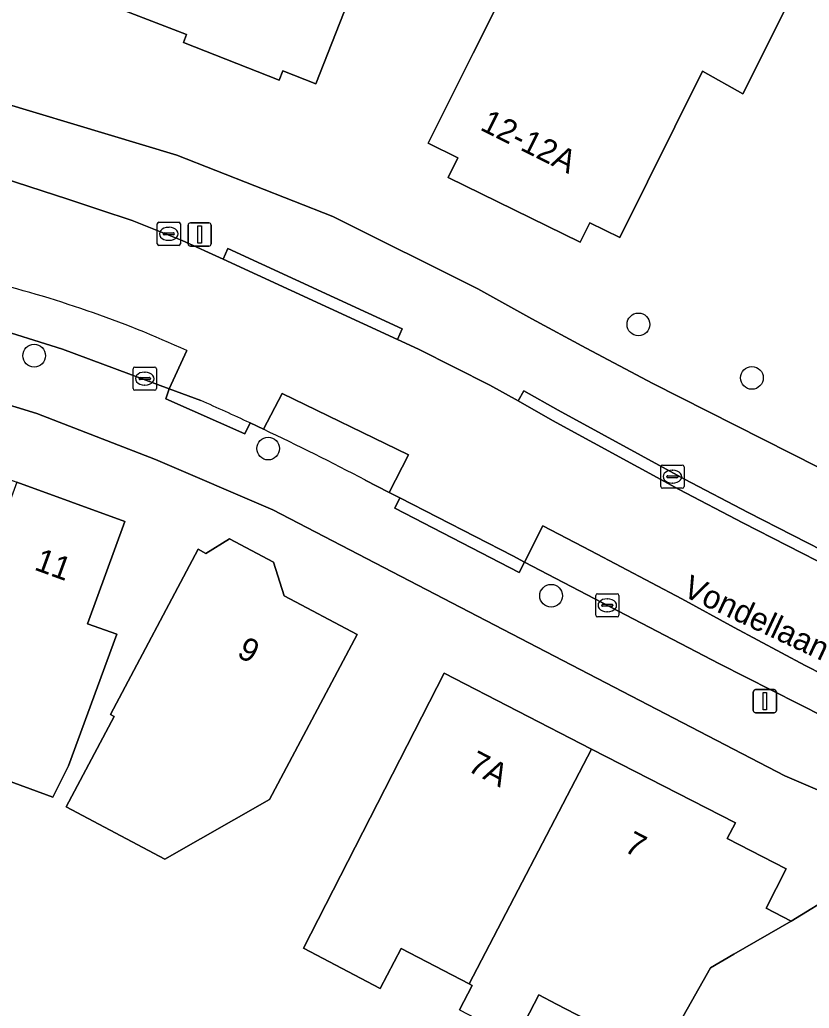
# Model space of a CAD drawing. Extents: x 161347 to 161881, y 382161 to 382804.
# Drawn here: x 161679.82 to 161713.79, y 382471.64 to 382514.18 of the extents above; entities that cross this region are included whole.
import ezdxf

# ---------------------------------------------------------------- set-up
doc = ezdxf.new("R2010")
doc.units = 0
for name, color, linetype in [('IMGEO_Boom', 7, 'Continuous'), ('IMGEO_Erf', 7, 'Continuous'), ('IMGEO_Groenvoorziening', 7, 'Continuous'), ('IMGEO_Kolk', 7, 'Continuous'), ('IMGEO_Lichtmast', 7, 'Continuous'), ('IMGEO_Openbare_ruimte_label', 7, 'Continuous'), ('IMGEO_Pand', 7, 'Continuous'), ('IMGEO_Pand_nummerreeks', 7, 'Continuous'), ('IMGEO_Parkeervlak_open', 7, 'Continuous'), ('IMGEO_Rijbaan_lokaal_open', 7, 'Continuous'), ('IMGEO_Voetpad_open', 7, 'Continuous')]:
    doc.layers.add(name, color=color, linetype=linetype)

msp = doc.modelspace()

# ---------------------------------------------------------------- linework, layer by layer
at = {"layer": 'IMGEO_Boom'}
for centre in [(161706.441, 382501.07), (161680.442, 382499.723), (161711.325, 382498.768), (161690.51, 382495.726), (161702.684, 382489.393)]:
    msp.add_circle(centre, 0.489, dxfattribs=at)
at = {"layer": 'IMGEO_Erf'}
for points in [[(161696.188, 382520.662), (161692.567, 382511.427), (161691.144, 382511.985), (161690.987, 382511.583), (161686.863, 382513.2), (161686.999, 382513.547), (161681.847, 382515.536)], [(161713.495, 382516.124), (161710.939, 382510.999), (161709.201, 382511.967), (161705.646, 382504.803), (161704.346, 382505.443), (161703.935, 382504.612), (161698.261, 382507.398), (161698.673, 382508.24), (161697.4, 382508.875), (161699.331, 382512.737), (161701.067, 382516.209)], [(161671.192, 382513.811), (161672.294, 382513.039), (161676.079, 382511.506), (161686.582, 382508.346), (161693.296, 382505.713), (161699.526, 382502.596), (161701.857, 382501.312), (161704.194, 382500.041), (161707.056, 382498.523), (161714.17, 382494.92), (161716.027, 382493.968), (161718.402, 382492.765), (161721.484, 382491.299)], [(161698.747, 382471.577), (161699.289, 382472.618), (161699.158, 382472.686), (161696.228, 382474.214), (161695.33, 382472.493), (161692.025, 382474.218), (161698.082, 382486.058), (161704.428, 382482.795), (161710.614, 382479.614), (161710.267, 382478.938), (161712.804, 382477.633), (161711.935, 382475.943), (161713.011, 382475.39), (161718.908, 382479.002), (161712.747, 382481.646), (161690.713, 382493.092), (161685.666, 382495.251), (161680.55, 382497.241), (161676.089, 382498.604), (161670.239, 382500), (161669.342, 382500.214)], [(161704.159, 382471.171), (161702.916, 382471.819), (161702.158, 382472.215), (161701.167, 382470.315)]]:
    msp.add_lwpolyline(points, dxfattribs=at)
for points in [[(161669.27, 382483.151), (161672.468, 382492.008), (161673.845, 382491.507), (161675.419, 382495.83), (161679.692, 382494.275), (161684.337, 382492.585), (161682.738, 382488.19), (161683.994, 382487.733), (161681.915, 382482.074), (161681.248, 382480.722), (161677.868, 382481.963), (161675.514, 382482.827), (161675.014, 382481.469)], [(161681.819, 382480.303), (161683.885, 382484.2), (161683.726, 382484.284), (161687.493, 382491.396), (161687.832, 382491.216), (161688.84, 382491.848), (161690.745, 382490.839), (161691.193, 382489.381), (161694.333, 382487.718), (161690.573, 382480.619), (161686.068, 382478.054)]]:
    msp.add_lwpolyline(points, close=True, dxfattribs=at)
at = {"layer": 'IMGEO_Groenvoorziening'}
msp.add_lwpolyline([(161723.237, 382475.454), (161722.614, 382477.411), (161718.908, 382479.002), (161713.011, 382475.39), (161710.549, 382473.96), (161709.541, 382473.374), (161708.224, 382471.041), (161709.207, 382469.376), (161711.307, 382469.157), (161714.949, 382470.071)], close=True, dxfattribs=at)
at = {"layer": 'IMGEO_Kolk'}
for p, q in [((161685.733, 382504.541), (161685.733, 382505.393)), ((161685.808, 382505.467), (161686.66, 382505.467)), ((161686.734, 382505.393), (161686.734, 382504.541)), ((161685.992, 382504.961), (161685.992, 382504.973)), ((161686.035, 382505.01), (161686.433, 382505.01)), ((161686.221, 382505.247), (161686.246, 382505.247)), ((161686.476, 382504.973), (161686.476, 382504.961)), ((161686.43, 382504.924), (161686.032, 382504.924)), ((161686.244, 382504.687), (161686.219, 382504.687)), ((161686.66, 382504.467), (161685.808, 382504.467)), ((161684.699, 382498.309), (161684.699, 382499.161)), ((161684.774, 382499.235), (161685.626, 382499.235)), ((161685.187, 382499.015), (161685.212, 382499.015)), ((161685.7, 382499.161), (161685.7, 382498.309)), ((161684.958, 382498.729), (161684.958, 382498.741)), ((161685.396, 382498.692), (161684.998, 382498.692)), ((161685.001, 382498.778), (161685.399, 382498.778)), ((161685.442, 382498.741), (161685.442, 382498.729)), ((161685.626, 382498.235), (161684.774, 382498.235)), ((161685.21, 382498.455), (161685.185, 382498.455)), ((161707.403, 382494.09), (161707.403, 382494.942)), ((161707.478, 382495.016), (161708.33, 382495.016)), ((161707.891, 382494.796), (161707.916, 382494.796)), ((161708.404, 382494.942), (161708.404, 382494.09)), ((161707.662, 382494.51), (161707.662, 382494.522)), ((161708.1, 382494.473), (161707.702, 382494.473)), ((161707.705, 382494.559), (161708.103, 382494.559)), ((161708.146, 382494.522), (161708.146, 382494.51)), ((161708.33, 382494.016), (161707.478, 382494.016)), ((161707.914, 382494.236), (161707.889, 382494.236)), ((161704.603, 382488.554), (161704.603, 382489.406)), ((161704.678, 382489.48), (161705.53, 382489.48)), ((161705.091, 382489.26), (161705.116, 382489.26)), ((161705.604, 382489.406), (161705.604, 382488.554)), ((161704.862, 382488.974), (161704.862, 382488.986)), ((161705.3, 382488.937), (161704.902, 382488.937)), ((161704.905, 382489.023), (161705.303, 382489.023)), ((161705.346, 382488.986), (161705.346, 382488.974)), ((161705.53, 382488.48), (161704.678, 382488.48)), ((161705.114, 382488.7), (161705.089, 382488.7))]:
    msp.add_line(p, q, dxfattribs=at)
for points in [[(161685.733, 382504.541), (161685.733, 382505.393)], [(161685.808, 382505.467), (161686.66, 382505.467)], [(161686.734, 382505.393), (161686.734, 382504.541)], [(161686.66, 382504.467), (161685.808, 382504.467)], [(161684.699, 382498.309), (161684.699, 382499.161)], [(161684.774, 382499.235), (161685.626, 382499.235)], [(161685.7, 382499.161), (161685.7, 382498.309)], [(161685.626, 382498.235), (161684.774, 382498.235)], [(161707.403, 382494.09), (161707.403, 382494.942)], [(161707.478, 382495.016), (161708.33, 382495.016)], [(161708.404, 382494.942), (161708.404, 382494.09)], [(161708.33, 382494.016), (161707.478, 382494.016)], [(161704.603, 382488.554), (161704.603, 382489.406)], [(161704.678, 382489.48), (161705.53, 382489.48)], [(161705.604, 382489.406), (161705.604, 382488.554)], [(161705.53, 382488.48), (161704.678, 382488.48)]]:
    msp.add_lwpolyline(points, dxfattribs=at)
for centre, radius, start, end in [((161685.81, 382505.391), 0.0765, 91.552, 178.448), ((161685.81, 382505.391), 0.0765, 91.552, 178.448), ((161686.658, 382505.391), 0.0765, 1.552, 88.448), ((161686.658, 382505.391), 0.0765, 1.552, 88.448), ((161686.032, 382504.97), 0.0403, 85.8775, 175.7526), ((161686.029, 382504.96), 0.0366, 178.938, 274.7102), ((161686.433, 382504.967), 0.043, 264.8664, 352.4533), ((161686.437, 382504.972), 0.0386, 1.7309, 96.639), ((161685.81, 382504.543), 0.0765, 181.552, 268.448), ((161685.81, 382504.543), 0.0765, 181.552, 268.448), ((161686.658, 382504.543), 0.0765, 271.552, 358.448), ((161686.658, 382504.543), 0.0765, 271.552, 358.448), ((161684.776, 382499.159), 0.0765, 91.552, 178.448), ((161684.776, 382499.159), 0.0765, 91.552, 178.448), ((161685.624, 382499.159), 0.0765, 1.552, 88.448), ((161685.624, 382499.159), 0.0765, 1.552, 88.448), ((161684.998, 382498.738), 0.0403, 85.8775, 175.7526), ((161684.995, 382498.728), 0.0366, 178.938, 274.7102), ((161685.399, 382498.735), 0.043, 264.8664, 352.4533), ((161685.403, 382498.74), 0.0386, 1.7309, 96.639), ((161684.776, 382498.311), 0.0765, 181.552, 268.448), ((161684.776, 382498.311), 0.0765, 181.552, 268.448), ((161685.624, 382498.311), 0.0765, 271.552, 358.448), ((161685.624, 382498.311), 0.0765, 271.552, 358.448), ((161707.48, 382494.94), 0.0765, 91.552, 178.448), ((161707.48, 382494.94), 0.0765, 91.552, 178.448), ((161708.328, 382494.94), 0.0765, 1.552, 88.448), ((161708.328, 382494.94), 0.0765, 1.552, 88.448), ((161707.702, 382494.519), 0.0403, 85.8775, 175.7526), ((161707.699, 382494.509), 0.0366, 178.938, 274.7102), ((161708.103, 382494.516), 0.043, 264.8664, 352.4533), ((161708.107, 382494.521), 0.0386, 1.7309, 96.639), ((161707.48, 382494.092), 0.0765, 181.552, 268.448), ((161707.48, 382494.092), 0.0765, 181.552, 268.448), ((161708.328, 382494.092), 0.0765, 271.552, 358.448), ((161708.328, 382494.092), 0.0765, 271.552, 358.448), ((161704.68, 382489.404), 0.0765, 91.552, 178.448), ((161704.68, 382489.404), 0.0765, 91.552, 178.448), ((161705.528, 382489.404), 0.0765, 1.552, 88.448), ((161705.528, 382489.404), 0.0765, 1.552, 88.448), ((161704.902, 382488.983), 0.0403, 85.8775, 175.7526), ((161704.899, 382488.973), 0.0366, 178.938, 274.7102), ((161705.303, 382488.98), 0.043, 264.8664, 352.4533), ((161705.307, 382488.985), 0.0386, 1.7309, 96.639), ((161704.68, 382488.556), 0.0765, 181.552, 268.448), ((161704.68, 382488.556), 0.0765, 181.552, 268.448), ((161705.528, 382488.556), 0.0765, 271.552, 358.448), ((161705.528, 382488.556), 0.0765, 271.552, 358.448)]:
    msp.add_arc(centre, radius, start, end, dxfattribs=at)
for centre, major_axis, ratio, start_param, end_param in [((161686.22, 382504.967), (-0.387, 0.002), 0.722429, 4.712389, 7.853982), ((161686.245, 382504.967), (-0.39, 0.002), 0.717154, 1.570796, 4.712389), ((161685.186, 382498.735), (-0.387, 0.002), 0.722429, 4.712389, 7.853982), ((161685.211, 382498.735), (-0.39, 0.002), 0.717154, 1.570796, 4.712389), ((161707.89, 382494.516), (-0.387, 0.002), 0.722429, 4.712389, 7.853982), ((161707.915, 382494.516), (-0.39, 0.002), 0.717154, 1.570796, 4.712389), ((161705.09, 382488.98), (-0.387, 0.002), 0.722429, 4.712389, 7.853982), ((161705.115, 382488.98), (-0.39, 0.002), 0.717154, 1.570796, 4.712389)]:
    msp.add_ellipse(centre, major_axis=major_axis, ratio=ratio, start_param=start_param, end_param=end_param, dxfattribs=at)
at = {"layer": 'IMGEO_Lichtmast'}
for p, q in [((161687.165, 382505.438), (161687.955, 382505.438)), ((161687.955, 382505.438), (161687.165, 382505.438)), ((161687.065, 382504.538), (161687.065, 382505.338)), ((161687.065, 382505.338), (161687.065, 382504.538)), ((161688.055, 382505.338), (161688.055, 382504.538)), ((161688.055, 382504.538), (161688.055, 382505.338)), ((161687.955, 382504.438), (161687.165, 382504.438)), ((161687.165, 382504.438), (161687.955, 382504.438)), ((161711.386, 382484.453), (161711.386, 382485.253)), ((161711.386, 382485.253), (161711.386, 382484.453)), ((161711.486, 382485.353), (161712.276, 382485.353)), ((161712.276, 382485.353), (161711.486, 382485.353)), ((161712.376, 382485.253), (161712.376, 382484.453)), ((161712.376, 382484.453), (161712.376, 382485.253)), ((161712.276, 382484.353), (161711.486, 382484.353)), ((161711.486, 382484.353), (161712.276, 382484.353))]:
    msp.add_line(p, q, dxfattribs=at)
for points in [[(161687.485, 382505.313), (161687.635, 382505.313), (161687.635, 382504.563), (161687.485, 382504.563), (161687.485, 382505.313)], [(161711.806, 382485.228), (161711.956, 382485.228), (161711.956, 382484.478), (161711.806, 382484.478), (161711.806, 382485.228)]]:
    msp.add_lwpolyline(points, dxfattribs=at)
for centre, start, end in [((161687.165, 382505.338), 90, 180), ((161687.165, 382505.338), 90, 180), ((161687.955, 382505.338), 0, 90), ((161687.955, 382505.338), 360, 90), ((161687.165, 382504.538), 180, 270), ((161687.165, 382504.538), 180, 270), ((161687.955, 382504.538), 270, 0), ((161687.955, 382504.538), 270, 0), ((161711.486, 382485.253), 90, 180), ((161711.486, 382485.253), 90, 180), ((161712.276, 382485.253), 0, 90), ((161712.276, 382485.253), 360, 90), ((161711.486, 382484.453), 180, 270), ((161711.486, 382484.453), 180, 270), ((161712.276, 382484.453), 270, 0), ((161712.276, 382484.453), 270, 0)]:
    msp.add_arc(centre, 0.1, start, end, dxfattribs=at)
at = {"layer": 'IMGEO_Pand'}
for points in [[(161718.281, 382530.16), (161705.209, 382536.63), (161704.863, 382535.846), (161702.913, 382531.424), (161702.78, 382531.122), (161701.407, 382528.011), (161701.274, 382527.709), (161701.108, 382527.333), (161705.884, 382524.94), (161701.422, 382516.032), (161701.067, 382516.209), (161699.331, 382512.737), (161697.4, 382508.875), (161698.673, 382508.24), (161698.261, 382507.398), (161703.935, 382504.612), (161704.346, 382505.443), (161705.646, 382504.803), (161709.201, 382511.967), (161710.939, 382510.999), (161713.495, 382516.124), (161711.723, 382517.008)], [(161701.067, 382516.209), (161701.422, 382516.032), (161705.884, 382524.94), (161701.108, 382527.333), (161697.513, 382528.711), (161695.912, 382524.537), (161686.722, 382528.062), (161681.847, 382515.536), (161686.999, 382513.547), (161686.863, 382513.2), (161690.987, 382511.583), (161691.144, 382511.985), (161692.567, 382511.427), (161696.188, 382520.662), (161699.202, 382519.424), (161698.274, 382517.607), (161698.645, 382517.421)], [(161675.514, 382482.827), (161677.868, 382481.963), (161681.248, 382480.722), (161681.915, 382482.074), (161683.994, 382487.733), (161682.738, 382488.19), (161684.337, 382492.585), (161679.692, 382494.275), (161676.515, 382485.55)], [(161690.573, 382480.619), (161694.333, 382487.718), (161691.193, 382489.381), (161690.745, 382490.839), (161688.84, 382491.848), (161687.832, 382491.216), (161687.493, 382491.396), (161683.726, 382484.284), (161683.885, 382484.2), (161681.819, 382480.303), (161686.068, 382478.054)], [(161699.158, 382472.686), (161704.428, 382482.795), (161698.082, 382486.058), (161692.025, 382474.218), (161695.33, 382472.493), (161696.228, 382474.214)], [(161713.011, 382475.39), (161711.935, 382475.943), (161712.804, 382477.633), (161710.267, 382478.938), (161710.614, 382479.614), (161704.428, 382482.795), (161699.158, 382472.686), (161699.289, 382472.618), (161698.747, 382471.577), (161701.167, 382470.315), (161702.158, 382472.215), (161702.916, 382471.819), (161704.159, 382471.171), (161704.376, 382469.995), (161704.404, 382469.845), (161704.876, 382469.993), (161708.224, 382471.041), (161709.541, 382473.374), (161710.549, 382473.96)]]:
    msp.add_lwpolyline(points, close=True, dxfattribs=at)
at = {"layer": 'IMGEO_Parkeervlak_open'}
for points in [[(161678.3, 382502.959), (161677.758, 382501.202), (161678.45, 382501.003), (161681.661, 382500), (161686.249, 382498.297), (161687.01, 382499.945)], [(161694.691, 382494.363), (161695.713, 382493.839), (161696.542, 382495.455), (161691.119, 382498.101), (161690.311, 382496.555)], [(161702.326, 382492.399), (161701.544, 382490.843), (161709.924, 382486.455), (161714.468, 382484.16)], [(161723.236, 382480.362), (161723.813, 382482.015), (161718.183, 382484.152), (161716.769, 382484.785), (161713.618, 382486.383), (161710.568, 382488.031), (161708.308, 382489.257), (161704.396, 382491.323), (161702.326, 382492.399)]]:
    msp.add_lwpolyline(points, dxfattribs=at)
for centre, radius, start, end in [((161666.702, 382455.35), 49.001, 65.516, 76.3088), ((161641.429, 382393.408), 114.144, 62.18466, 64.64339)]:
    msp.add_arc(centre, radius, start, end, dxfattribs=at)
at = {"layer": 'IMGEO_Rijbaan_lokaal_open'}
for points in [[(161719.242, 382488.369), (161716.458, 382489.726), (161714.753, 382490.583), (161710.935, 382492.532), (161708.189, 382493.967), (161702.751, 382496.934), (161701.262, 382497.773), (161700.052, 382498.454), (161696.974, 382500), (161696.072, 382500.419), (161688.569, 382503.883), (161686.809, 382504.682), (161684.661, 382505.544), (161683.272, 382506.002), (161681.884, 382506.459), (161679.107, 382507.366), (161677.108, 382508.026), (161674.333, 382508.996)], [(161687.01, 382499.945), (161686.249, 382498.297), (161687.609, 382497.792)], [(161689.729, 382496.829), (161690.311, 382496.555), (161691.119, 382498.101), (161696.542, 382495.455), (161695.713, 382493.839), (161696.181, 382493.599), (161701.035, 382491.11), (161701.544, 382490.843), (161702.326, 382492.399), (161704.396, 382491.323), (161708.308, 382489.257), (161710.568, 382488.031), (161713.618, 382486.383), (161716.769, 382484.785), (161718.183, 382484.152), (161723.813, 382482.015), (161723.236, 382480.362), (161723.942, 382480.108), (161726.799, 382479.176), (161728.624, 382478.622)]]:
    msp.add_lwpolyline(points, dxfattribs=at)
for centre, radius, start, end in [((161666.702, 382455.35), 49.001, 65.516, 76.3088), ((161643.812, 382398.56), 108.468, 64.95531, 66.18529)]:
    msp.add_arc(centre, radius, start, end, dxfattribs=at)
at = {"layer": 'IMGEO_Voetpad_open'}
for points in [[(161701.857, 382501.312), (161699.526, 382502.596), (161693.296, 382505.713), (161686.582, 382508.346), (161676.079, 382511.506), (161672.294, 382513.039), (161671.192, 382513.811), (161668.846, 382512.65)], [(161674.333, 382508.996), (161677.108, 382508.026), (161679.107, 382507.366), (161681.884, 382506.459), (161683.272, 382506.002), (161684.661, 382505.544), (161686.809, 382504.682), (161688.569, 382503.883), (161688.779, 382504.336), (161696.282, 382500.872), (161696.072, 382500.419), (161696.974, 382500), (161700.052, 382498.454), (161701.262, 382497.773), (161701.505, 382498.21), (161702.99, 382497.373), (161708.428, 382494.406), (161711.162, 382492.977), (161714.98, 382491.028), (161719.46, 382488.819)], [(161690.311, 382496.555), (161689.729, 382496.829), (161689.509, 382496.361), (161686.101, 382497.862), (161686.249, 382498.297), (161681.661, 382500), (161678.45, 382501.003), (161678.326, 382500.519), (161671.031, 382502.373), (161671.155, 382502.857), (161670.674, 382502.94), (161667.582, 382503.472)], [(161721.484, 382491.299), (161718.402, 382492.765), (161716.027, 382493.968), (161714.17, 382494.92), (161707.056, 382498.523), (161704.194, 382500.041), (161701.857, 382501.312)], [(161669.342, 382500.214), (161670.239, 382500), (161676.089, 382498.604), (161680.55, 382497.241), (161685.666, 382495.251), (161690.713, 382493.092), (161712.747, 382481.646), (161718.908, 382479.002), (161722.614, 382477.411), (161727.934, 382475.503)], [(161687.609, 382497.792), (161686.249, 382498.297), (161686.101, 382497.862), (161689.509, 382496.361), (161689.729, 382496.829)], [(161714.98, 382491.028), (161711.162, 382492.977), (161708.428, 382494.406), (161702.99, 382497.373), (161701.505, 382498.21), (161701.262, 382497.773), (161702.751, 382496.934), (161708.189, 382493.967), (161710.935, 382492.532), (161714.753, 382490.583), (161716.458, 382489.726), (161719.242, 382488.369)], [(161701.544, 382490.843), (161701.317, 382490.398), (161695.954, 382493.154), (161696.181, 382493.599), (161695.713, 382493.839), (161694.691, 382494.363)], [(161714.468, 382484.16), (161709.924, 382486.455), (161701.544, 382490.843)]]:
    msp.add_lwpolyline(points, dxfattribs=at)
for points in [[(161696.072, 382500.419), (161696.282, 382500.872), (161688.779, 382504.336), (161688.569, 382503.883)], [(161701.544, 382490.843), (161701.035, 382491.11), (161696.181, 382493.599), (161695.954, 382493.154), (161701.317, 382490.398)]]:
    msp.add_lwpolyline(points, close=True, dxfattribs=at)
for centre, radius, start, end in [((161643.812, 382398.56), 108.468, 64.95531, 66.18529), ((161641.429, 382393.408), 114.144, 62.18466, 64.64339)]:
    msp.add_arc(centre, radius, start, end, dxfattribs=at)

# ---------------------------------------------------------------- texts
at = {"layer": 'IMGEO_Openbare_ruimte_label'}
msp.add_text('Vondellaan', height=1, rotation=334.9208, dxfattribs=at).set_placement((161708.286, 382489.412))
at = {"layer": 'IMGEO_Pand_nummerreeks'}
for s, rotation, p in [('12-12A', 333.4892, (161699.583, 382509.462)), ('11', 340.005, (161680.402, 382490.526)), ('9', 331.7322, (161689.118, 382486.798)), ('7A', 332.7876, (161699.039, 382481.878)), ('7', 332.7902, (161705.776, 382478.415))]:
    msp.add_text(s, height=1, rotation=rotation, dxfattribs=at).set_placement(p)

doc.saveas('drawing.dxf')
